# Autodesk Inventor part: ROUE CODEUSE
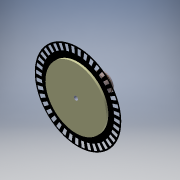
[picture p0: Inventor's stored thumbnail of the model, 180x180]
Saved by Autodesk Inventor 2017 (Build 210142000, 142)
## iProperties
Created: 2013-10
Part Number: ROUE CODEUSE
Material: Générique
Document SubType Name: Modeling
Designer: Bruno
Density: 1 g/cm^3
Appearance: Par défaut
Mass: 6.43183 g
Surface Area: 79.9554 cm^2
Volume: 6.43183 cm^3
Sending System: SolidWorks 2013
Last Author: JG
Last Saved: 2014-02-15
Author: Bruno
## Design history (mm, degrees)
feature "Enlèv. mat.-Extru.2"
sketch "Esquisse1"
  geometry: C1 r 7.561 at (0, 0); A1 r 56 centre (-50.164, 39.033) between (-103.875, 23.187) and (3.838, 24.208) reference; 1 further point
  constraints: 1 centre point, 1 coincident, 1 tangent
feature "SrfExtrusion1" sketch "Esquisse1" dims "d0" = 22, "d1" = 0
node "Solide1"
node "Référence1"
body "Srf1"
